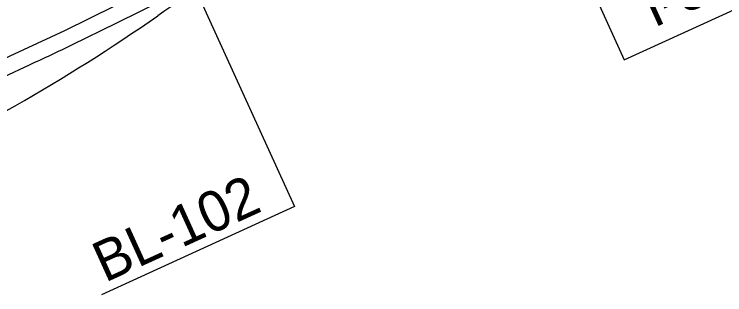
# Model space of a CAD drawing. Extents: x 2243531 to 2252747, y 658714 to 667210.
# Drawn here: x 2249747 to 2250626, y 663321 to 663667 of the extents above; entities that cross this region are included whole.
import ezdxf

# ---------------------------------------------------------------- set-up
doc = ezdxf.new("R2010")
doc.units = 0
for name, color, linetype in [('CTL NGS Horizontal CELL', 7, 'Continuous'), ('CTL Supplemental Horizontal and Vertical Text', 7, 'Continuous'), ('Exist Roads EOP', 7, 'Continuous'), ('Prop Horizontal Alignment', 7, 'Continuous')]:
    doc.layers.add(name, color=color, linetype=linetype)

msp = doc.modelspace()

# ---------------------------------------------------------------- linework, layer by layer
at = {"layer": 'CTL NGS Horizontal CELL'}
for p, q in [((2250383.09, 663870.53), (2250501.32, 663611.07)), ((2250501.32, 663611.07), (2251034.19, 663853.89)), ((2249954.97, 663733.91), (2250093.64, 663429.6)), ((2250093.64, 663429.6), (2249854.75, 663320.75))]:
    msp.add_line(p, q, dxfattribs=at)
at = {"layer": 'Exist Roads EOP'}
for points in [[(2250076.16, 663777.96), (2250011.04, 663745.73), (2249959.41, 663720.2), (2249871.12, 663677.1), (2249809.32, 663646.75), (2249741.67, 663615.28), (2249682.29, 663587.16), (2249593.6, 663545.55), (2249601.8, 663528.84), (2249642.54, 663547.1), (2249701.92, 663575.09), (2249765.85, 663604.94)], [(2250076.16, 663777.96), (2250011.04, 663745.73), (2249959.41, 663720.2), (2249871.12, 663677.1), (2249809.32, 663646.75), (2249741.67, 663615.28), (2249682.29, 663587.16), (2249593.6, 663545.55), (2249601.8, 663528.84), (2249642.54, 663547.1), (2249701.92, 663575.09), (2249765.85, 663604.94)], [(2249819.23, 663629.9), (2249873.17, 663656.29), (2249935.79, 663687.42), (2249991.5, 663714.36)], [(2249819.23, 663629.9), (2249873.17, 663656.29), (2249935.79, 663687.42), (2249991.5, 663714.36)]]:
    msp.add_lwpolyline(points, dxfattribs=at)
msp.add_ellipse((2249136.15, 665022.47), major_axis=(-545.8, -1452.11), ratio=0.999747, start_param=0.777697, end_param=0.815691, dxfattribs=at)
msp.add_ellipse((2249136.15, 665022.47), major_axis=(-545.8, -1452.11), ratio=0.999747, start_param=0.777697, end_param=0.815691, dxfattribs=at)
at = {"layer": 'Prop Horizontal Alignment'}
for centre, start, end in [((2251237.28, 661776.78), 117.57881, 124.80379), ((2248611.75, 665553.89), 294.41783, 304.80379)]:
    msp.add_arc(centre, 2300, start, end, dxfattribs=at)

# ---------------------------------------------------------------- texts
at = {"layer": 'CTL Supplemental Horizontal and Vertical Text'}
for s, height, p in [('I-3318BB-GPS3', 49.9994, (2250538.4, 663650.24)), ('BL-102', 49.999, (2249859.26, 663335.35))]:
    msp.add_text(s, height=height, rotation=24.49794, dxfattribs=at).set_placement(p)

doc.saveas('drawing.dxf')
